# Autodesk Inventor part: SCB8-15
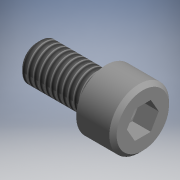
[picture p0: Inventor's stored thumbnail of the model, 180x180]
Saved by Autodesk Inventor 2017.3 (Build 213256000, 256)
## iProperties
Part Number: SCB8-15
Material: Generic
Catalog Web Link: www.cadenas.de
Description: SCB-Hexagon Socket Head Cap Screws - Stainless Steel
Vendor: MISUMI
Document SubType Name: Modeling
Designer: partserver
Manufacturer: MISUMI
Mass: 1.6641 g
Surface Area: 10.2129 cm^2
Volume: 1.6641 cm^3
Density: 1 g/cm^3
Appearance: PSOLRGB-175-175-175
Category: PARTsolutions
Company: MISUMI
Title: SCB8-15
Author: Cadenas PARTsolutions
Comments: Hexagon Socket Head Cap Screws - Stainless Steel
PSOL_IDENT_0: {$CADENAS_DATA\23d-libs\misumi\metric\27_screws_nuts\scb_fa.prj},154 {VTYP=3D},{NB=SCB8-15},{LINA=SC
PSOL_IDENT_1: B8-15},{NN=SCB},{DATE=03.06.2021 03:35:43},{GEOMDATE=23.02.2012 00:00:00},{VERSION=},{LINEID=110},{W
PSOL_IDENT_2: BVAR=L},{WBNUMERIC=L}  {NB=SCB8-15},{LINA=SCB8-15},{KT=DUMMY},{PN=SCB8-15},{MAT=SUSXM7(30430 Stainle
PSOL_IDENT_3: ss Steel)},{SC=A2-70},{M=8},{L=15},{LL=Full Thread},{L1=28},{TYPE=SCB},{M1=8.0},{L0=10,12,14,15,16,1
PSOL_IDENT_4: 8,20,22,25,30,35,40,45,50,55,60,65,70,75,80},{MP=8x1.25},{P=1.25},{A=13.0},{E=8.0},{B=6.0},{V=0.80}
NB: SCB8-15
NN: SCB
NT: Hexagon Socket Head Cap Screws - Stainless Steel
NBSYN: $PN.
LINA: SCB8-15
CATALOG: Misumi
PN: SCB8-15
MAT: 302HQ Stainless Steel
SC: A2-70
M: 8
L: 15
LL: Full Thread
MP: 8x1.25
A: 13
E: 8
B: 6
SUPPLIER: MISUMI
ARTICLENO: SCB8-15
BOMINFO: SCB8-15
CREATOR: CADENAS GmbH
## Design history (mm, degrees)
sketch "Sketch_1"
  geometry: L1 (15, 0)-(-8, 0); L2 (-8, 0)-(-8, 5.7); L3 (-8, 5.7)-(-7.2, 6.5); L4 (-7.2, 6.5)-(0, 6.5); L5 (0, 6.5)-(0, 4); L6 (0, 4)-(14.233, 4); L7 (14.233, 4)-(15, 3.233); L8 (15, 3.233)-(15, 0); L9 (15, 0)-(-8, 0)
  constraints: 18 end point
revolve "Revolution1" sketch "Sketch_1" stored, may be unused: angle "d0" = 360 deg
thread "Thread1" dims "d1" = 12.983, "d2" = 0
sketch "Sketch2"
  geometry: 1 further point
hole "Hole1" sketch "Sketch2" at (0, 0) diameter "d3" = 6; stored, may be unused: countersink angle "d7" = 90 deg, drill point angle "d9" = 150 deg; dims "d4" = 6, "d5" = 4, "d6" = 2, "d8" = 4
sketch "Sketch_3"
  geometry: L1 (-3, -1.732)-(0, -3.464); L2 (0, -3.464)-(3, -1.732); L3 (3, -1.732)-(3, 1.732); L4 (3, 1.732)-(0, 3.464); L5 (0, 3.464)-(-3, 1.732); L6 (-3, 1.732)-(-3, -1.732)
  constraints: 12 end point
extrude "Extrusion1" cut sketch "Sketch_3" distance "d10" = 4; taper "d11" = 0 deg
node "bolt_XY"
node "bolt_YZ"
node "bolt_ZX"
node "bolt_X"
node "bolt_Y"
node "bolt_Z"
node "bolt_Center"
node "nut_XY"
node "nut_YZ"
node "nut_ZX"
node "nut_X"
node "nut_Y"
node "nut_Z"
node "nut_Center"
body "Solid1"
other parameters: "d12" = 0, "d13" = 0
